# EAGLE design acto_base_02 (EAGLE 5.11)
AUTHOR: Michael Mehling
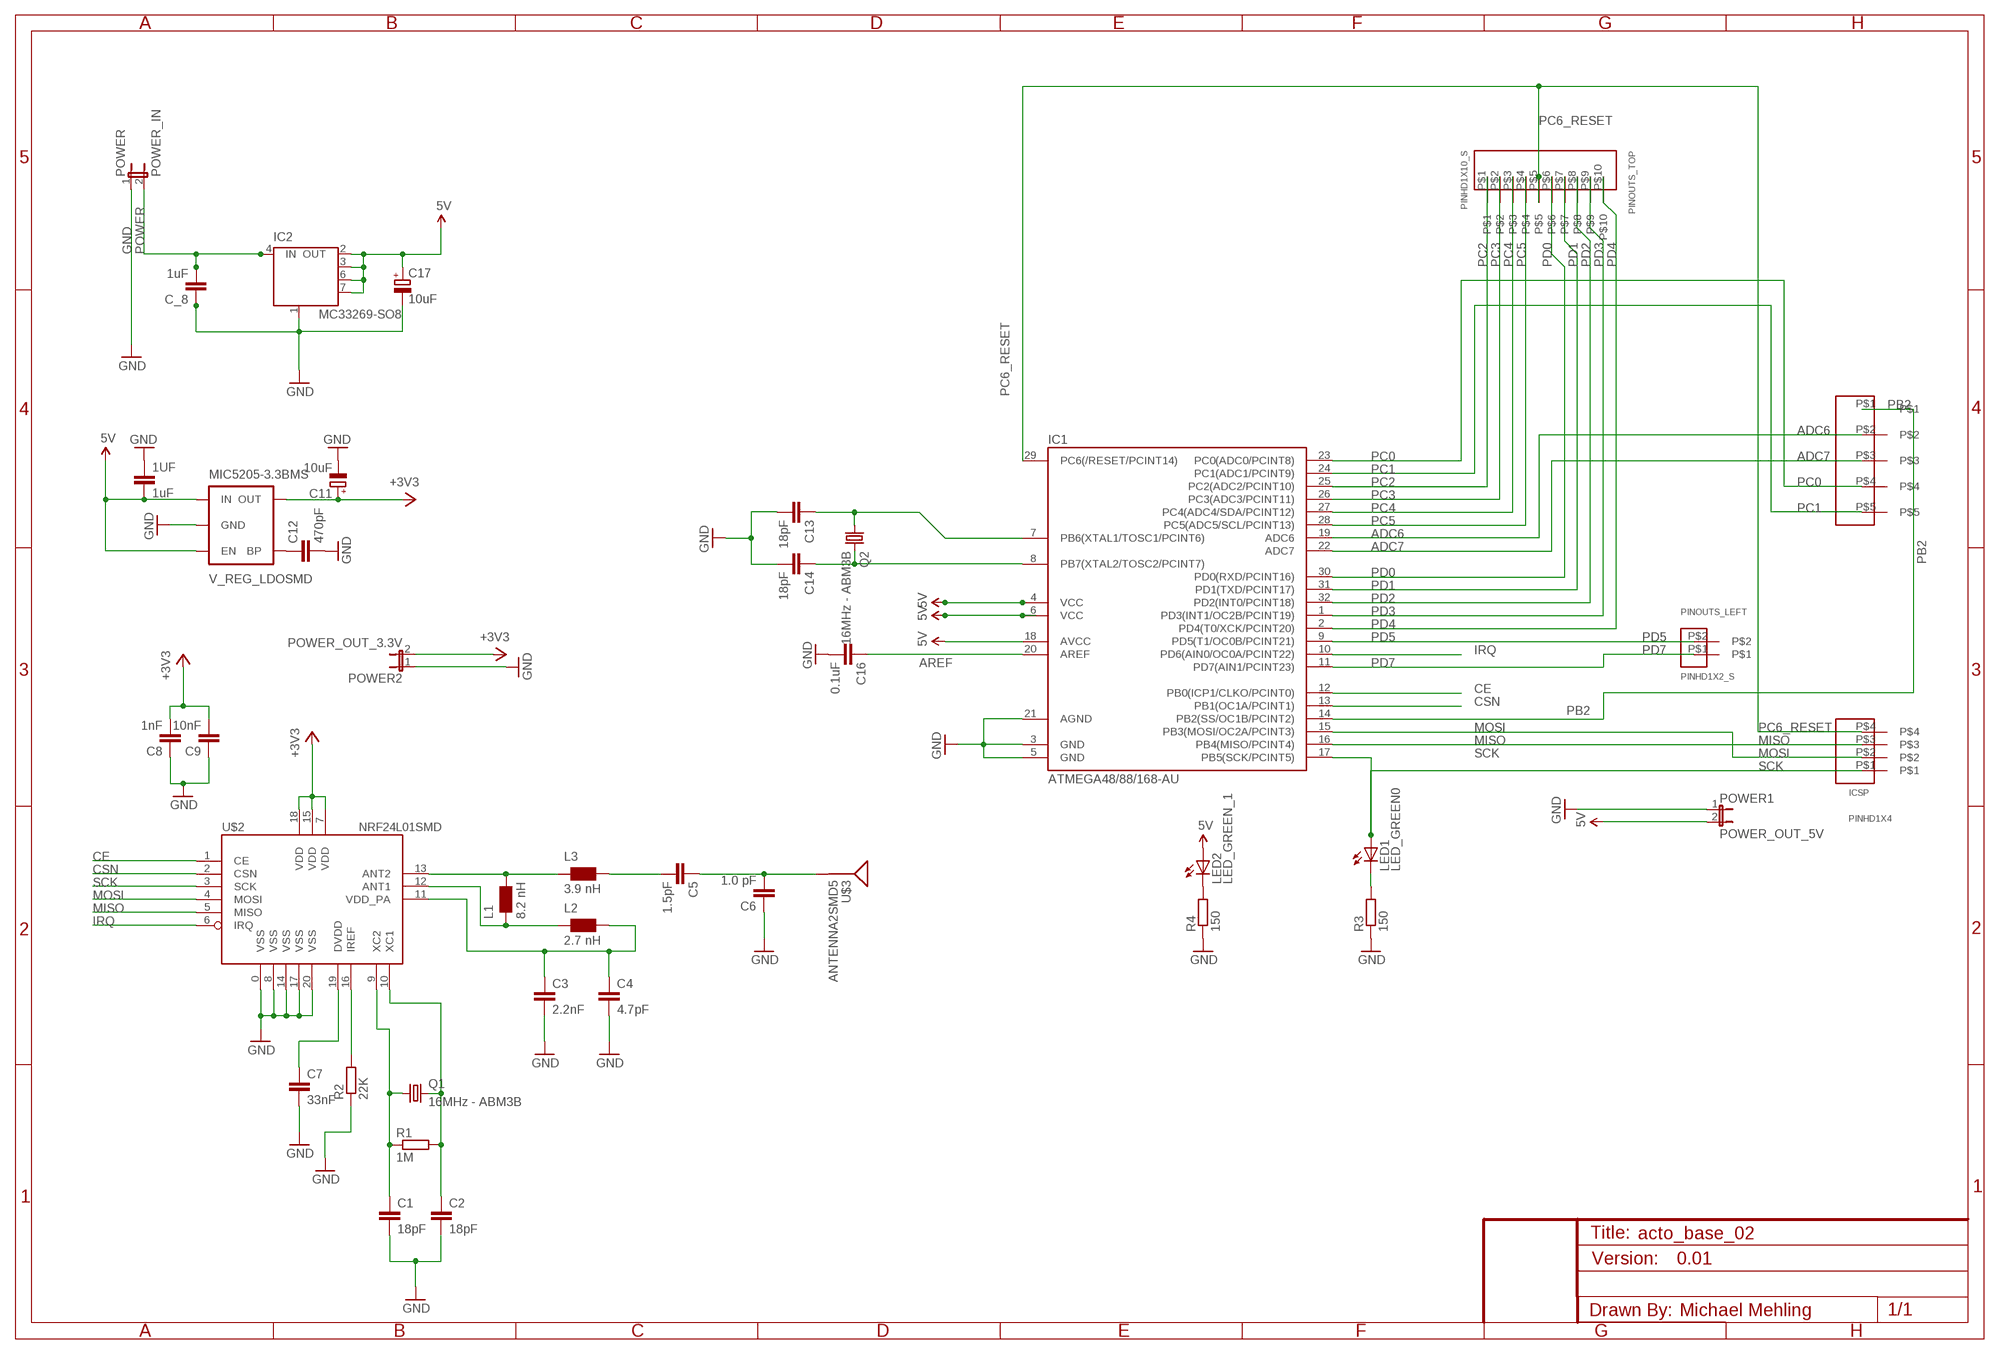
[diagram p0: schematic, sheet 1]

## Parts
1UF  1uF  C-EUC0603  [C0603]
C1  18pF  C-EUC0402  [C0402]
C2  18pF  C-EUC0402  [C0402]
C3  2.2nF  C-EUC0402  [C0402]
C4  4.7pF  C-EUC0402  [C0402]
C5  1.5pF  C-EUC0402  [C0402]
C6  1.0 pF  C-EUC0402  [C0402]
C7  33nF  C-EUC0402  [C0402]
C8  1nF  C-EUC0402  [C0402]
C9  10nF  C-EUC0402  [C0402]
C11  10uF  CPOL-EUA/3216-18R  [A/3216-18R]
C12  470pF  C-EUC0603  [C0603]
C13  18pF  C-EUC0603  [C0603]
C14  18pF  C-EUC0603  [C0603]
C16  0.1uF  C-EUC0402  [C0402]
C17  10uF  CPOL-EUA/3216-18R  [A/3216-18R]
C_8  1uF  C-EUC0805  [C0805]
IC1  ATMEGA48/88/168-AU  [TQFP32-08]
IC2  MC33269-SO8  [SO08]
ICSP  PINHD1X4  [PINHD1X4_S]
L1  8.2 nH  WE-CBF_0402  [0402]
L2  2.7 nH  WE-CBF_0402  [0402]
L3  3.9 nH  WE-CBF_0402  [0402]
LED1  LED_GREEN0  LED0603  [LED-0603]
LED2  LED_GREEN_1  LED0603  [LED-0603]
MIC5205-3.3BMS  V_REG_LDOSMD  [SOT23-5]
PINOUTS_LEFT  PINHD1X2_S  [PINHD1X2_S]
PINOUTS_RIGHT  PINHD1X5_S  [PINHD1X5_S]
PINOUTS_TOP  PINHD1X10_S  [PINHD1X10_S]
POWER  POWER_IN  JUMPER-2PTH  [1X02]
POWER1  POWER_OUT_5V  JUMPER-2PTH  [1X02]
POWER2  POWER_OUT_3.3V  JUMPER-2PTH  [1X02]
Q1  16MHz - ABM3B  CRYSTAL5X3  [CRYSTAL-SMD-5X3]
Q2  16MHz - ABM3B  CRYSTAL5X3  [CRYSTAL-SMD-5X3]
R1  1M  R-EU_R0402  [R0402]
R2  22K  R-EU_R0402  [R0402]
R3  150  R-EU_R0402  [R0402]
R4  150  R-EU_R0402  [R0402]
U$2  NRF24L01SMD  [QFN20]
U$3  ANTENNA2SMD5  [ANTENNA-CHIP5]

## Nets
5V: 1UF.2 C17.+ IC1.4(VCC) IC1.6(VCC) IC1.18(AVCC) IC2.2(OUT) IC2.3(OUT) IC2.6(OUT) IC2.7(OUT) LED2.A MIC5205-3.3BMS.1(IN) MIC5205-3.3BMS.3(EN) POWER1.2
+3V3: C8.2 C9.2 C11.+ MIC5205-3.3BMS.5(OUT) POWER2.2 U$2.7(VDD) U$2.15(VDD) U$2.18(VDD)
ADC6: IC1.19(ADC6) PINOUTS_RIGHT.P$2
ADC7: IC1.22(ADC7) PINOUTS_RIGHT.P$3
AREF: C16.1 IC1.20(AREF)
CE: IC1.12(PB0(ICP1/CLKO/PCINT0)) U$2.1(CE)
CSN: IC1.13(PB1(OC1A/PCINT1)) U$2.2(CSN)
GND: 1UF.1 C1.2 C2.2 C3.2 C4.2 C6.1 C7.2 C8.1 C9.1 C11.- C12.2 C13.2 C14.2 C16.2 C17.- C_8.1 IC1.3(GND) IC1.5(GND) IC1.21(AGND) IC2.1(GND/ADJ) MIC5205-3.3BMS.2(GND) POWER1.1 POWER2.1 POWER.1 R2.1 R3.1 R4.1 U$2.0(VSS) U$2.8(VSS) U$2.14(VSS) U$2.17(VSS) U$2.20(VSS)
IRQ: IC1.10(PD6(AIN0/OC0A/PCINT22)) U$2.6(IRQ)
MISO: IC1.16(PB4(MISO/PCINT4)) ICSP.P$3 U$2.5(MISO)
MOSI: IC1.15(PB3(MOSI/OC2A/PCINT3)) ICSP.P$2 U$2.4(MOSI)
N$1: L1.2 L3.1 U$2.13(ANT2)
N$2: R2.2 U$2.16(IREF)
N$3: C1.1 Q1.1 R1.1 U$2.9(XC2)
N$5: C2.1 Q1.3 R1.2 U$2.10(XC1)
N$6: C7.1 U$2.19(DVDD)
N$7: C5.2 L3.2
N$8: C5.1 C6.2 U$3.FEED(SIGNAL)
N$9: L1.1 L2.1 U$2.12(ANT1)
N$10: C3.1 C4.1 L2.2 U$2.11(VDD_PA)
N$28: C13.1 IC1.7(PB6(XTAL1/TOSC1/PCINT6)) Q2.1
N$29: C14.1 IC1.8(PB7(XTAL2/TOSC2/PCINT7)) Q2.3
N$30: LED1.C R3.2
N$31: LED2.C R4.2
N$32: C12.1 MIC5205-3.3BMS.4(BP)
PB2: IC1.14(PB2(SS/OC1B/PCINT2)) PINOUTS_RIGHT.P$1
PC0: IC1.23(PC0(ADC0/PCINT8)) PINOUTS_RIGHT.P$4
PC1: IC1.24(PC1(ADC1/PCINT9)) PINOUTS_RIGHT.P$5
PC2: IC1.25(PC2(ADC2/PCINT10)) PINOUTS_TOP.P$1
PC3: IC1.26(PC3(ADC3/PCINT11)) PINOUTS_TOP.P$2
PC4: IC1.27(PC4(ADC4/SDA/PCINT12)) PINOUTS_TOP.P$3
PC5: IC1.28(PC5(ADC5/SCL/PCINT13)) PINOUTS_TOP.P$4
PC6_RESET: IC1.29(PC6(/RESET/PCINT14)) ICSP.P$4 PINOUTS_TOP.P$5
PD0: IC1.30(PD0(RXD/PCINT16)) PINOUTS_TOP.P$6
PD1: IC1.31(PD1(TXD/PCINT17)) PINOUTS_TOP.P$7
PD2: IC1.32(PD2(INT0/PCINT18)) PINOUTS_TOP.P$8
PD3: IC1.1(PD3(INT1/OC2B/PCINT19)) PINOUTS_TOP.P$9
PD4: IC1.2(PD4(T0/XCK/PCINT20)) PINOUTS_TOP.P$10
PD5: IC1.9(PD5(T1/OC0B/PCINT21)) PINOUTS_LEFT.P$2
PD7: IC1.11(PD7(AIN1/PCINT23)) PINOUTS_LEFT.P$1
POWER: C_8.2 IC2.4(IN) POWER.2
SCK: IC1.17(PB5(SCK/PCINT5)) ICSP.P$1 LED1.A U$2.3(SCK)

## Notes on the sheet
- 0.01
- Michael Mehling

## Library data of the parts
1UF C1-C9 C12-C14 C16 C_8 = rcl:C-EU: CAPACITOR, European symbol
C11 C17 = rcl:CPOL-EU: POLARIZED CAPACITOR, European symbol
IC1 = atmega8:ATMEGA48/88/168
IC2 = linear:MC33269-SO8: Adjustable Output Low Dropout Voltage Regulator 800 mA Source: http://www.onsemi.com/pub/Collateral/MC33269-D.PDF
ICSP = MyLibs:PINHD1X4
L1-L3 = wuerth-elektronik:WE-CBF: SMD EMI Suppression Ferrite Beads
LED1 LED2 = SparkFun:LED: LEDs
MIC5205-3.3BMS = SparkFun:V_REG_LDO: Voltage Regulator LDO Standard 150mA LDO voltage regulator in SOT-23 layout. Micrel part MIC5205. BP (by-pass) pin is used to lower output noise with 470pF cap.
PINOUTS_LEFT = MyLibs:PINHD1X2_S
PINOUTS_RIGHT = MyLibs:PINHD1X5_S
PINOUTS_TOP = MyLibs:PINHD1X10_S
POWER POWER1 POWER2 = SparkFun:JUMPER-2: Jumper
Q1 Q2 = SparkFun:CRYSTAL: Crystals
R1 R2 = resistor:R-EU_: RESISTOR, European symbol
R3 R4 = rcl:R-EU_: RESISTOR, European symbol
U$2 = SparkFun:NRF24L01: 2.4GHz Low Power Transceiver This is the very popular, low cost, very low power RF transceiver from Nordic Semiconductor. Simple SPI interface. SKU: COM-00690
U$3 = SparkFun:ANTENNA2: Antenna

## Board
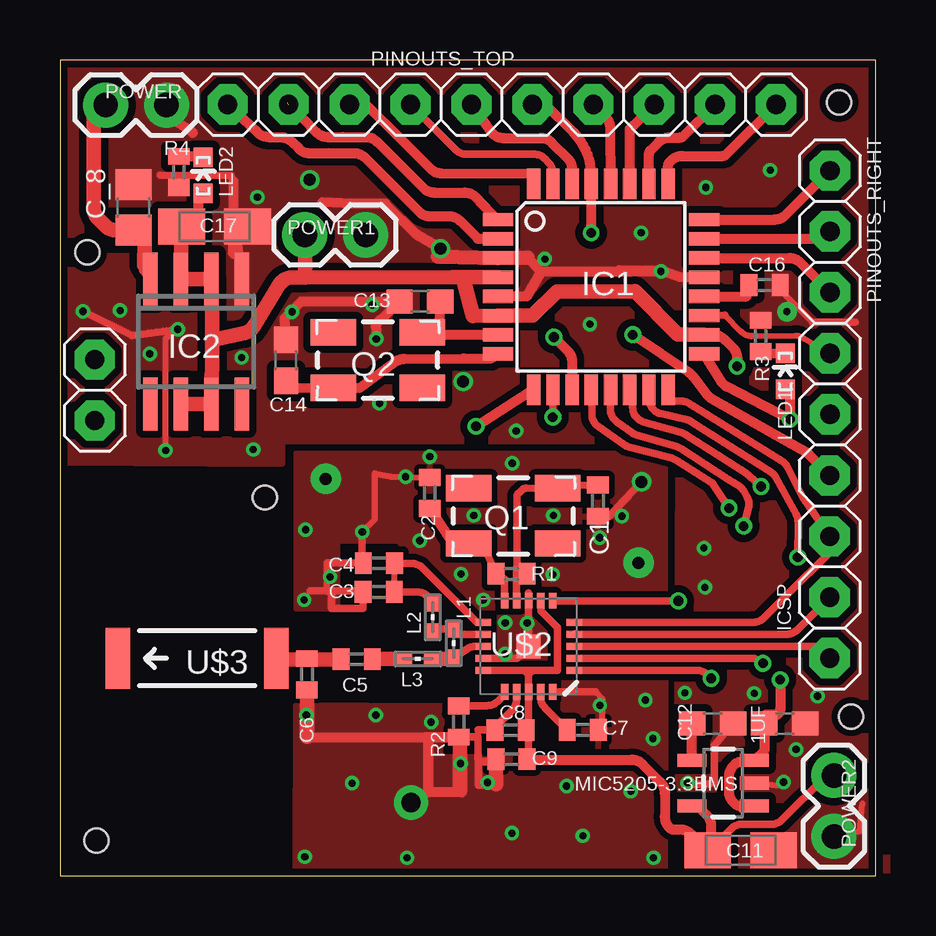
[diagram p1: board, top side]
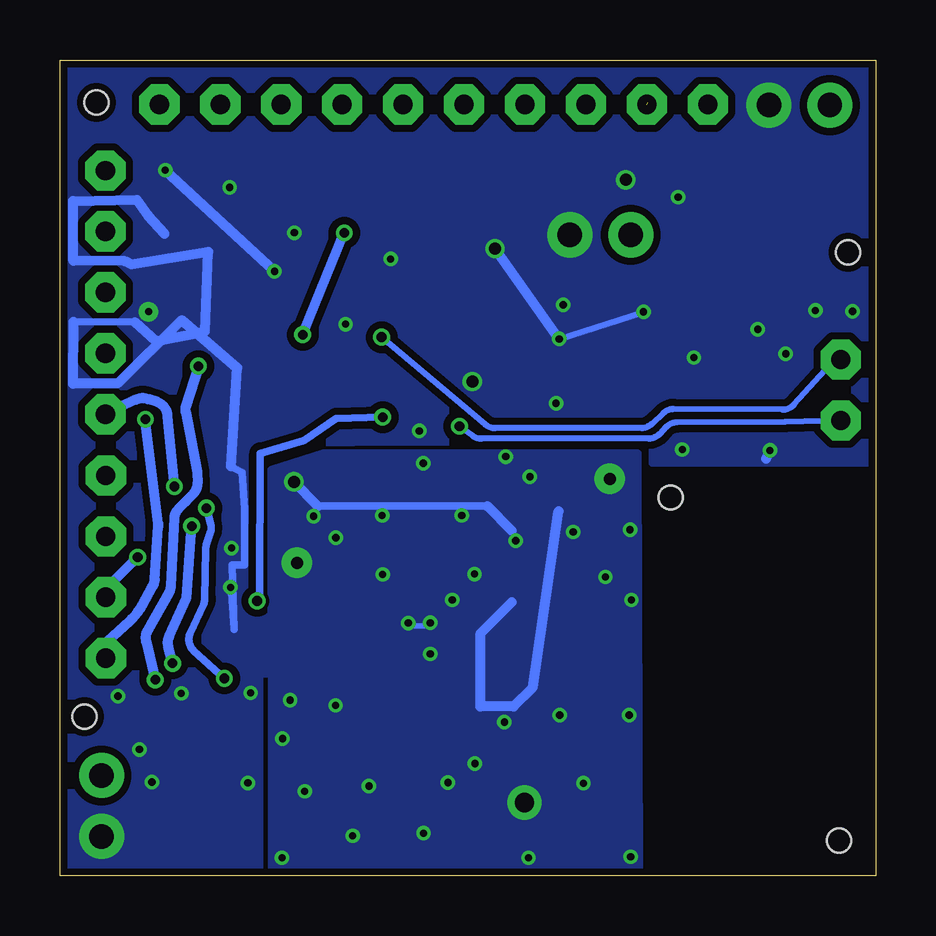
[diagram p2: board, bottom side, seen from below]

Size 34 x 34 mm. Coordinates in mm from the lower left corner, seen from the top.
Outline: 0,0 34,0 34,34 0,34 0,0
Copper layers (1*16): Top 0.035mm / dielectric 1.5mm / Bottom 0.035mm
Design rules "PCB-POOL Standard": minimum track width 0.15mm, minimum drill 0.3mm, track to track 0.15mm, track to pad 0.15mm, pad to pad 0.15mm, via to via 0.15mm, smd to smd 0.15mm, copper to edge 0.3mm, drill to drill 0.2mm, minimum pad ring 0.2mm, minimum via ring 0.15mm, stop-mask expansion 0.075mm, vias tented up to drill 0mil, thermal gap 0.2mm
Holes 1 mm at 32.97,6.63 32.48,32.24 1.15,25.98 1.51,1.47 8.53,15.76

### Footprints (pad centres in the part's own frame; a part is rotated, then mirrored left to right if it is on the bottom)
C0603 = smd 1.1 x 1: 1 -0.85,0; 2 0.85,0
C0402 = smd 0.7 x 0.9: 1 -0.65,0; 2 0.65,0
A/3216-18R = smd 1.95 x 1.5: + 1.375,0; - -1.375,0
C0805 = smd 1.3 x 1.5: 1 -0.95,0; 2 0.95,0
TQFP32-08 = smd 1.27 x 0.559: 1 -4.293,2.8; 2 -4.293,2; 3 -4.293,1.2; 4 -4.293,0.4; 5 -4.293,-0.4; 6 -4.293,-1.2; 7 -4.293,-2; 8 -4.293,-2.8; 17 4.293,-2.8; 18 4.293,-2; 19 4.293,-1.2; 20 4.293,-0.4; 21 4.293,0.4; 22 4.293,1.2; 23 4.293,2; 24 4.293,2.8 | smd 0.559 x 1.27: 9 -2.8,-4.293; 10 -2,-4.293; 11 -1.2,-4.293; 12 -0.4,-4.293; 13 0.4,-4.293; 14 1.2,-4.293; 15 2,-4.293; 16 2.8,-4.293; 25 2.8,4.293; 26 2,4.293; 27 1.2,4.293; 28 0.4,4.293; 29 -0.4,4.293; 30 -1.2,4.293; 31 -2,4.293; 32 -2.8,4.293
SO08 = smd 0.6 x 2.2: 1 -1.905,-2.6; 2 -0.635,-2.6; 3 0.635,-2.6; 4 1.905,-2.6; 5 1.905,2.6; 6 0.635,2.6; 7 -0.635,2.6; 8 -1.905,2.6
PINHD1X4_S = drill 0.8 pad 1.676 octagon: P$1 0,3.81; P$2 0,1.27; P$3 0,-1.27; P$4 0,-3.81
0402 = smd 0.7 x 0.6: 1 -0.6,0; 2 0.6,0
LED-0603 = smd 0.8 x 0.8: A 0,-0.75; C 0,0.75
SOT23-5 = smd 0.55 x 1.2: 1 -0.95,-1.3; 2 0,-1.3; 3 0.95,-1.3; 4 0.95,1.3; 5 -0.95,1.3
PINHD1X2_S = drill 0.8 pad 1.676 octagon: P$1 0,-1.27; P$2 0,1.27
PINHD1X5_S = drill 0.8 pad 1.676 octagon: P$1 0,-5.08; P$2 0,-2.54; P$3 0,0; P$4 0,2.54; P$5 0,5.08
PINHD1X10_S = drill 0.8 pad 1.676 octagon: P$1 0,-11.43; P$2 0,-8.89; P$3 0,-6.35; P$4 0,-3.81; P$5 0,-1.27; P$6 0,1.27; P$7 0,3.81; P$8 0,6.35; P$9 0,8.89; P$10 0,11.43
1X02 = drill 1.016 pad 1.88 round: 1 0,0; 2 2.54,0
CRYSTAL-SMD-5X3 = smd 1.9 x 1.1: 1 -1.85,-1.15; 2 1.85,-1.15; 3 1.85,1.15; 4 -1.85,1.15
R0402 = smd 0.7 x 0.9: 1 -0.65,0; 2 0.65,0
QFN20 = smd 1 x 1: 0 0,0 | smd 0.65 x 0.3: 1 -1.9,1; 2 -1.9,0.5; 3 -1.9,0; 4 -1.9,-0.5; 5 -1.9,-1; 11 1.9,-1; 12 1.9,-0.5; 13 1.9,0; 14 1.9,0.5; 15 1.9,1 | smd 0.3 x 0.65: 6 -1,-1.9; 7 -0.5,-1.9; 8 0,-1.9; 9 0.5,-1.9; 10 1,-1.9; 16 1,1.9; 17 0.5,1.9; 18 0,1.9; 19 -0.5,1.9; 20 -1,1.9
ANTENNA-CHIP5 = smd 1.016 x 2.54: FEED -3.302,0; NC 3.302,0

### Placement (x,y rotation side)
1UF  30.21,6.35 180 top
C1  22.43,15.63 270 top
C2  15.42,15.95 90 top
C3  13.29,11.82 180 top
C4  13.29,13.02 180 top
C5  12.37,9.02 0 top
C6  10.3,8.39 90 top
C7  21.8,6.07 0 top
C8  18.78,6.06 0 top
C9  18.82,4.86 0 top
C11  28.37,1.05 180 top
C12  27.21,6.33 0 top
C13  15.01,23.94 180 top
C14  9.43,21.48 90 top
C16  29.37,24.62 0 top
C17  6.45,27.06 180 top
C_8  3.07,27.85 270 top
IC1  22.55,24.54 0 top
IC2  5.68,22.26 180 top
ICSP  32.09,12.87 180 top
L1  16.42,9.68 270 top
L2  15.54,10.77 90 top
L3  14.92,9.03 180 top
LED1  30.24,21.02 0 top
LED2  5.97,29.18 0 top
MIC5205-3.3BMS  27.65,3.86 90 top
PINOUTS_LEFT  1.45,20.24 180 top
PINOUTS_RIGHT  32.1,24.31 0 top
PINOUTS_TOP  18.43,32.14 90 top
POWER  4.45,32.12 180 top
POWER1  12.75,26.71 180 top
POWER2  32.27,1.63 90 top
Q1  18.9,14.99 180 top
Q2  13.25,21.49 180 top
R1  18.83,12.58 180 top
R2  16.62,6.42 90 top
R3  29.21,22.5 270 top
R4  4.96,29.33 90 top
U$2  19.54,9.56 180 top
U$3  5.72,9.06 180 top

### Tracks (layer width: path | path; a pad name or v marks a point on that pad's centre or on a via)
5V  (via drill 0.4 pad 0.25)
  Top 0.305: 5.07,27.3 4.84,27.54 4.66,27.54
  Top 0.406: 23.94,24.34 23.96,24.36 | IC1.18 27.3,22.52 arc-42 27.72,22.34 28.04,22.02 arc-47 28.23,21.56 v28.23,21.23 | MIC5205-3.3BMS.1 28.61,2.86 arc-97 27.89,3.49 27.89,4.13 arc-53 28.14,4.64 28.24,4.71 MIC5205-3.3BMS.3 | MIC5205-3.3BMS.3 29.35,4.76 | 4.81,26.85 C17.+ 5.07,27.3 5.79,27.3 5.79,28.25 LED2.A | 4.66,27.54 | 16.39,24.95 16.79,24.9 | v30.02,8.16 30.03,6.95 arc-53 29.91,6.7 29.41,6.7 1UF.2 29.36,5.2 MIC5205-3.3BMS.3
  Top 0.61: IC1.18 25.76,22.56 23.96,24.36 | 23.94,24.34 20.71,24.34 19.7,23.34 18.98,23.34 IC1.6 17.22,23.33 16.79,24.9 | IC2.6 IC2.7 6.34,22.31 | 6.34,22.31 IC2.2 IC2.3 5.05,26.66 4.81,26.85 | 10.22,24.93 16.39,24.95 IC1.4 | 6.34,22.31 7.69,22.62 arc46 8.09,22.91 9.14,24.63 arc-59 9.69,24.94 10.22,24.93 | 10.22,24.93 POWER1.2
  Bottom 0.406: v28.23,21.23 28.76,19.56 arc-20 28.77,19.33 28.27,16.82 28.27,16.35 arc44 28.45,15.91 28.75,15.59 29.08,15.26 arc-45 29.23,14.9 29.38,12.07 arc27 29.46,11.79 30.35,10.21 arc-43 30.41,9.75 v30.02,8.16
+3V3
  Top 0.254: U$2.18 | 19.54,5.79 C8.2 19.53,5.89 | C9.2 19.54,4.69
  Top 0.305: U$2.7 20.05,11.02 20.74,10.34 20.74,8.56 20.43,8.56 19.71,8.56 | 19.53,5.89 U$2.18 | 19.54,4.69 19.54,5.79 | POWER2.2 31.91,4.12 30.1,2.32 arc-45 29.66,2.14 28.43,2.14 arc45 27.98,1.95 27.36,1.33 C11.+ | U$2.18 19.54,8.38 | 19.54,8.38 19.37,8.56 | 19.54,8.38 19.71,8.56 | 19.71,8.56 U$2.15
  Top 0.406: C9.2 19.5,4.83 23.84,4.83 arc-45 24.29,4.64 25.03,3.89 arc-45 25.22,3.45 25.22,2.45 arc45 25.41,2 arc45 25.6,1.92 25.87,1.92 arc-45 26.32,1.73 C11.+ 27.15,1.16 27.15,2.07 arc45 26.97,2.52 26.58,2.91 MIC5205-3.3BMS.5
ADC6
  Top 0.254: 27.71,23.36 28.39,22.68 arc45 28.84,22.49 30.64,22.51 arc-30 30.97,22.42 PINOUTS_RIGHT.P$2
  Top 0.305: IC1.19 27.71,23.36
ADC7
  Top 0.406: IC1.22 30.41,25.74 arc-45 30.86,25.56 PINOUTS_RIGHT.P$3
AREF
  Top 0.406: IC1.20 28.62,24.14 C16.1
CE  (via drill 0.4)
  Top 0.305: IC1.12 22.17,19.23 arc54 22.44,18.72 23.52,17.96 arc21 23.72,17.87 25.51,17.4 arc-18 25.69,17.32 27.15,16.39 arc-24 27.23,16.32 v27.89,15.32 | U$2.1 26.55,8.56 arc-45 27,8.37 v27.15,8.22
  Bottom 0.305: v27.15,8.22 28.42,9.36 arc73 28.57,10.1 28.02,11.31 arc-24 27.96,11.56 27.93,13.58 arc18 27.9,13.77 27.73,14.28 arc-33 27.72,14.64 v27.89,15.32
CSN  (via drill 0.4, 0.4 pad 0.25)
  Top 0.305: IC1.13 22.95,19.43 arc55 23.21,18.91 23.85,18.46 arc19 24.04,18.37 25.71,17.88 arc-17 25.88,17.8 27.86,16.52 28.29,16.25 arc-28 28.5,16.03 28.64,15.8 arc-45 28.7,15.32 v28.51,14.57 | U$2.2 28.84,9.06 arc-45 29.28,8.87 v29.31,8.85
  Bottom 0.406: v29.31,8.85 29.48,9.56 arc38 29.45,9.97 28.72,11.58 v28.51,14.57
GND  (via drill 0.3, 0.3 pad 0.25, 0.3 pad 0.81, 0.5, 0.5 pad 0.25, 0.5 pad 0.81, 0.5 pad 1.27, 0.8 pad 1.42)
  Top 0.254: v4.4,17.72 4.41,22.41 v4.91,22.77 | v18.56,10.53 18.63,10.47 | 22.31,7.66 22.62,7.35 22.62,6.37 C7.2 | 18.32,6.36 18.32,5.81 C8.1 | C9.1 | 17.44,5.78 17.44,6.06 | 12.6,13.02 C4.2 12.64,13.04 | 11.14,11.81 11.14,13.03 | MIC5205-3.3BMS.2 29.88,3.76 | C11.- 29.79,1.32 | 33.45,3 33.34,1.84 POWER2.1 | C2.2 13.8,16.63 13.13,16.76 13.13,14.86 12.6,14.32 | C16.2 30.28,24.15 31.36,23.07 | 33.15,23.07 33.16,23.09
  Top 0.305: U$2.14 19.05,9.06 U$2.0 U$2.8 19.54,11.78 | v24.25,16.41 22.87,14.94 C1.2 | v4.91,22.77 3,22.51 v0.96,23.52 | 22.31,7.66 U$2.20 | 18.32,6.36 18.85,6.89 arc45 19.04,7.34 U$2.17 | R2.1 17.44,5.78 17.44,4.86 17.53,4.77 18.15,4.77 18.12,4.75 17.44,4.75 17.44,3.75 18.12,3.75 18.17,3.8 | 17.44,6.06 C8.1 | 12.6,13.02 12.6,14.32 | 11.14,13.03 12.64,13.04 | 31.36,23.07 33.15,23.07 | C12.2 27.28,5.44 27.27,3.86 26.93,3.81 26.11,3.81 | 7.24,28.95 7.13,29.19 4.18,29.2 | C3.2 12.64,11.13 11.32,11.13 11.32,11.86 | 11.32,11.86 12.71,11.86 | 11.32,11.86 10.43,11.86
  Top 0.406: IC1.5 19.45,24.14 20.05,25.18 | 20.05,25.18 25.14,25.2 | 19.48,25.76 20.05,25.18 | C14.2 9.36,23.24 10.07,23.94 C13.2 13.16,22.97 v13.19,22.37 | 15.76,25.81 v15.86,26.14 14.87,26.73 13.55,28.01 12.18,28.01 10.93,28.07 | 25.14,25.2 23.3,25.23 v25.05,25.19 | 25.14,25.2 25.81,24.96 IC1.21 | POWER.1 4.49,31.69 5.54,30.96 | 7.24,28.95 7.24,27.06 7.23,25.92 7.24,26.06 7.24,26.55 7.34,26.72 IC2.1 | R2.1 15.25,5.77 15.36,5.77 15.36,3.47 16.75,3.47 16.75,3.73 16.68,3.73 | 16.68,5.76 10.32,5.76 10.32,5.78
  Top 0.61: 19.48,25.76 IC1.3 15.76,25.81 | 10.3,5.78 C6.1 | 18.17,3.8 C9.1 | 16.68,5.76 16.68,3.73
  Bottom 0.254: v13.19,22.37 v9.68,23.5 | v18.56,10.53 18.78,10.41 19.54,10.38
  Bottom 0.305: 16.19,15.4 23.25,15.4 | 33.44,23.09 30.88,23.07 | 26.87,17.06 26.4,16.8 26.3,15.28 26.31,12.95 26.83,12.95 26.75,10.27 26.84,11.8 v26.89,12.01
  Bottom 0.406: v13.19,22.37 v15.86,26.14 | v25.05,25.19 v29.61,29.41 | 13.21,15.19 14.29,7.85 15.09,7.05 16.47,7.05 16.46,10.09 15.16,11.4 | 23.25,15.4 v24.25,16.41 | 15.16,14.37 16.19,15.4 | 26.87,17.06 26.61,21.16 28.92,23.15 31.6,20.51 33.45,20.51 33.44,23.09 | 30.88,23.07 30,22.27 27.95,22.68 27.82,26 31.01,25.47 31.29,25.61 33.45,25.63 33.45,28.12 30.8,28.17 30.34,27.54 29.64,26.75 | v4.4,17.72 4.57,17.38
  other vias: 30.16,3.89 22.09,22.98 20.22,25.7 11.08,16.53 30.3,23.51 15.47,6.4 22.51,7.09 24.72,5.71 26.05,7.61 8.05,17.76 8.23,28.28 13.32,19.69 19.02,18.53 16.81,20.59 10.41,29.01 3.74,21.75 13.02,23.79 7.57,21.6 24.23,26.8 26.93,28.68 28.94,7.59 26.17,3.86 30.69,5.26 31.59,7.48 19.48,10.53 24.12,13.03 18.56,9.24 10.27,6.69 13.17,6.69 10.21,0.78 14.47,0.74 16.7,4.67 17.83,3.88 20.55,12.55 17.65,11.49 16.72,12.57 15,13.96 10.18,11.49 10.24,14.42 12.61,14.32 14.41,16.62 15.42,17.46 22.5,14.08 23.43,14.98 24.74,0.74 23.8,3.51 21.12,3.73 18.84,1.76 14.64,3.04 17.25,15.01 20.57,15.01 2.51,23.56 12.18,3.85 26.85,13.65 11.26,12.45 24.41,7.31 18.85,17.19 21.8,1.66
  pour Bottom (isolate 0.305, no thermals): 13.76,18.16 9.29,18.24 9.26,17.23 -0.04,17.26 0,34.2 34.06,34.05 33.73,0.23 25.73,0.24 25.73,8.47 24.89,8.47 24.89,11.59 25.75,11.59 25.71,18.1
  pour Top (isolate 0.305, no thermals): 0.02,17.31 9.2,17.23 9.2,18.2 25.84,18.2 25.84,17.34 25.76,0.15 34.44,0.18 33.93,33.76 -0.15,34.28 -0.21,17.31
  pour Top (isolate 0.254, no thermals): 20.54,10.76 18.24,10.83 18.24,8.95 20.57,8.95 20.58,10.66
  pour Top (isolate 0.254): 9.87,11.17 9.86,16.64 9.86,17.6 25.22,17.6 25.22,11.12 17.74,11.16 16.59,11.19 14.09,13.95 11.55,13.92 11.54,11.11 9.86,11.12
  pour Top (isolate 0.254): 9.83,0.13 9.85,7.1 15.92,7.07 15.85,4.94 20.97,4.98 20.99,7.12 20.99,8.2 25.24,8.32 25.22,0.12
  pour Bottom: 9.89,0.12 9.94,17.56 22.99,17.55 25.16,16.87 25.14,0.11 9.85,0.11
IRQ  (via drill 0.4)
  Top 0.305: U$2.6 25.77,11.45 v25.78,11.45 | v20.55,19.11 IC1.10
  Bottom 0.305: v25.78,11.45 25.68,11.76 25.65,17.59 23.82,18.14 22.49,19.04 v20.55,19.11
MISO
  Top 0.305: IC1.16 25.52,19.79 25.87,19.79 arc-31 26.19,19.69 26.91,19.25 30.1,17.28 arc-31 30.33,17.03 30.98,15.75 arc8 31.02,15.68 ICSP.P$3 32.11,13.49 30.27,11.67 29.35,10.74 arc-45 28.9,10.56 U$2.5
MOSI  (via drill 0.4)
  Top 0.305: U$2.4 30.28,10.06 arc45 30.73,10.24 ICSP.P$2 | v30.76,13.27 30.77,14.74 arc29 30.69,15.05 29.84,16.59 arc29 29.63,16.82 27.16,18.38 26.31,18.92 arc19 26.11,19.01 25.05,19.25 arc-76 24.56,19.86 IC1.15
  Bottom 0.305: ICSP.P$2 32.09,11.65
  Bottom 0.406: ICSP.P$2 32.09,11.69 arc45 31.9,12.13 v30.76,13.27
N$1
  Top 0.254: 16.32,8.87 L1.2 16.37,9.03
  Top 0.305: L1.2 16.99,9.45 arc-33 17.33,9.56 U$2.13
  Top 0.61: 16.37,9.03 L3.1
N$2
  Top 0.254: 18.54,7.55 U$2.16 | R2.2 16.58,7.08
  Top 0.305: 16.58,7.08 17.8,7.08 arc45 18.25,7.27 18.54,7.55
N$3
  Top 0.254: 19.04,12.65 R1.1 19.04,12.71 | Q1.1 20.85,16.25
  Top 0.305: U$2.9 19.04,12.65 | 19.04,12.71 19.04,15.75 arc-45 19.12,15.93 19.26,16.07 arc-45 19.44,16.15 Q1.1 | 20.85,16.25 C1.1
N$5
  Top 0.254: 16.3,13.97 Q1.3 17.54,13.97 17.67,13.71
  Top 0.305: U$2.10 18.54,12.37 R1.2 17.67,13.71
  Top 0.406: 16.3,13.97 C2.1
N$6
  Top 0.305: U$2.19 20.04,7.43 arc45 20.23,6.98 C7.1
N$7
  Top 0.254: C5.2 13.03,9.03
  Top 0.61: 13.03,9.03 L3.2
N$8
  Top 0.254: 10.3,9.02 C6.2 | U$3.FEED 9.11,9.02
  Top 0.61: C5.1 10.3,9.02 9.11,9.02
N$9
  Top 0.254: 16.45,10.06 L1.1 | 15.58,10.28 L2.1
  Top 0.305: U$2.12 16.45,10.06 | L1.1 15.58,10.28
N$10
  Top 0.254: C3.1 C4.1 | 17.38,10.56 U$2.11
  Top 0.305: C3.1 14.89,11.82 arc-54 15.4,11.56 L2.2 | 17.38,10.56 16.9,11.03 16.8,11.13 15.11,12.83 arc45 14.66,13.02 C4.1
N$28
  Top 0.406: C13.1 15.83,23.01 Q2.1 15.66,22.55 IC1.7
N$29
  Top 0.406: C14.1 9.39,20.9 9.63,20.33 Q2.3 12.5,20.33 13.99,21.42 arc-36 14.36,21.54 16.84,21.56 17.98,21.56 IC1.8
N$30
  Top 0.406: LED1.C 29.39,21.76 R3.2
N$31
  Top 0.406: LED2.C 5.71,29.98 R4.2
N$32
  Top 0.406: MIC5205-3.3BMS.4 26.35,6.06 C12.1
PB2  (via drill 0.4)
  Top 0.305: IC1.14 23.88,19.43 arc66 24.33,18.91 25.9,18.47 arc-17 26.07,18.39 27.39,17.54 28.59,16.77 arc-9 28.71,16.68 v29.23,16.22
  Bottom 0.406: v29.23,16.22 29.52,19.13 arc-69 29.92,19.73 30.33,19.86 arc-47 30.84,19.84 PINOUTS_RIGHT.P$1
PC0
  Top 0.406: IC1.23 31.69,26.54 arc45 31.87,26.62 PINOUTS_RIGHT.P$4
PC1
  Top 0.406: IC1.24 29.8,27.35 arc45 30.25,27.53 PINOUTS_RIGHT.P$5
PC2
  Top 0.406: IC1.25 25.35,29.58 arc-45 25.43,29.75 25.48,29.81 arc-45 25.93,30 27.6,30 arc45 27.78,30.07 PINOUTS_TOP.P$1
PC3
  Top 0.406: IC1.26 24.55,30.06 arc-45 24.63,30.24 24.97,30.58 arc-45 25.42,30.77 25.83,30.77 arc45 26.01,30.84 PINOUTS_TOP.P$2
PC4
  Top 0.406: IC1.27 23.75,31.12 arc-19 23.94,31.3 PINOUTS_TOP.P$3
PC5
  Top 0.406: PINOUTS_TOP.P$4 22.75,31.63 arc-44 22.93,31.19 IC1.28
PC6_RESET  (via drill 0.4)
  Top 0.406: v23.88,22.55 26.23,20.96 arc-19 26.38,20.82 26.96,20.06 arc23 27.16,19.89 30.33,18.09 31.08,17.67 arc-16 31.22,17.56 ICSP.P$4 | v22.15,26.79 22.15,28.82 arc-45 IC1.29 22.15,29.19 arc45 21.41,30.98 20.25,32.14 PINOUTS_TOP.P$5
  Bottom 0.406: v23.88,22.55 v22.15,26.79
PD0
  Top 0.406: IC1.30 21.35,29.44 arc45 21.17,29.89 20.5,30.56 arc46 20.05,30.75 18.49,30.74 arc-55 17.97,31.01 PINOUTS_TOP.P$6
PD1
  Top 0.305: PINOUTS_TOP.P$7 16.48,30.26 arc45 16.93,30.07 19.77,30.07 arc-43 20.23,29.88 20.37,29.73 arc-44 20.55,29.29 IC1.31
PD2
  Top 0.406: IC1.32 19.82,29.27 15.9,29.27 arc-45 15.46,29.46 14.16,30.75 12.8,32.1 PINOUTS_TOP.P$8
PD3  (1 unrouted)
  Top 0.406: 9.5,32.23 10.71,30.98 arc46 11.16,30.78 11.79,30.78 11.76,30.78 12.77,30.78 arc-45 13.22,30.59 15.15,28.66 arc45 15.6,28.48 16.88,28.47 arc-46 17.33,28.28 18.25,27.33 IC1.1
PD4
  Top 0.406: IC1.2 17.42,26.54 16.67,27.3 arc43 16.22,27.49 15.42,27.48 arc-45 14.97,27.67 12.73,29.92 arc42 12.28,30.11 11.18,30.11 11.19,30.11 10.41,30.11 arc-45 9.96,30.29 9.66,30.59 arc43 9.23,30.77 8.67,30.79 arc-42 8.25,30.96 PINOUTS_TOP.P$10
PD5  (via drill 0.4)
  Top 0.406: IC1.9 19.64,20.21 v17.35,18.73
  Bottom 0.254: v17.35,18.73 16.78,18.33 arc-41 16.42,18.21 9.46,18.21 arc-47 9,18.41 8.73,18.69 arc47 8.27,18.89 3.76,18.92 PINOUTS_LEFT.P$2
PD7  (via drill 0.4)
  Top 0.406: v20.59,22.45 21.16,21.89 arc-46 21.35,21.44 IC1.11
  Bottom 0.254: v20.59,22.45 16.26,18.8 arc-42 15.85,18.65 9.76,18.65 arc-43 9.32,18.83 8.85,19.27 arc44 8.41,19.45 3.88,19.42 arc-48 3.4,19.63 1.66,21.55 PINOUTS_LEFT.P$1
POWER
  Top 0.406: IC2.4 3.5,25.23 3.51,25.44
  Top 0.61: 3.51,25.44 3.53,26.46 3.52,27.14 C_8.2 2.33,26.9 arc-45 1.88,27.09 1.58,27.39 arc-45 1.4,27.84 1.4,31.61 POWER.2
SCK  (via drill 0.4)
  Top 0.305: U$2.3 31.33,9.56 arc-45 31.78,9.37 ICSP.P$1
  Top 0.406: IC1.17 27.55,20.61 arc31 27.8,20.38 v30.44,19.02 30.44,20.03 30.3,20.28 LED1.A
  Bottom 0.305: ICSP.P$1 32.24,9.55
  Bottom 0.406: v30.44,19.02 29.9,14.67 arc11 29.9,14.55 30.05,12.34 arc25 30.13,12.07 30.57,11.26 arc19 31.08,10.62 32.24,9.55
